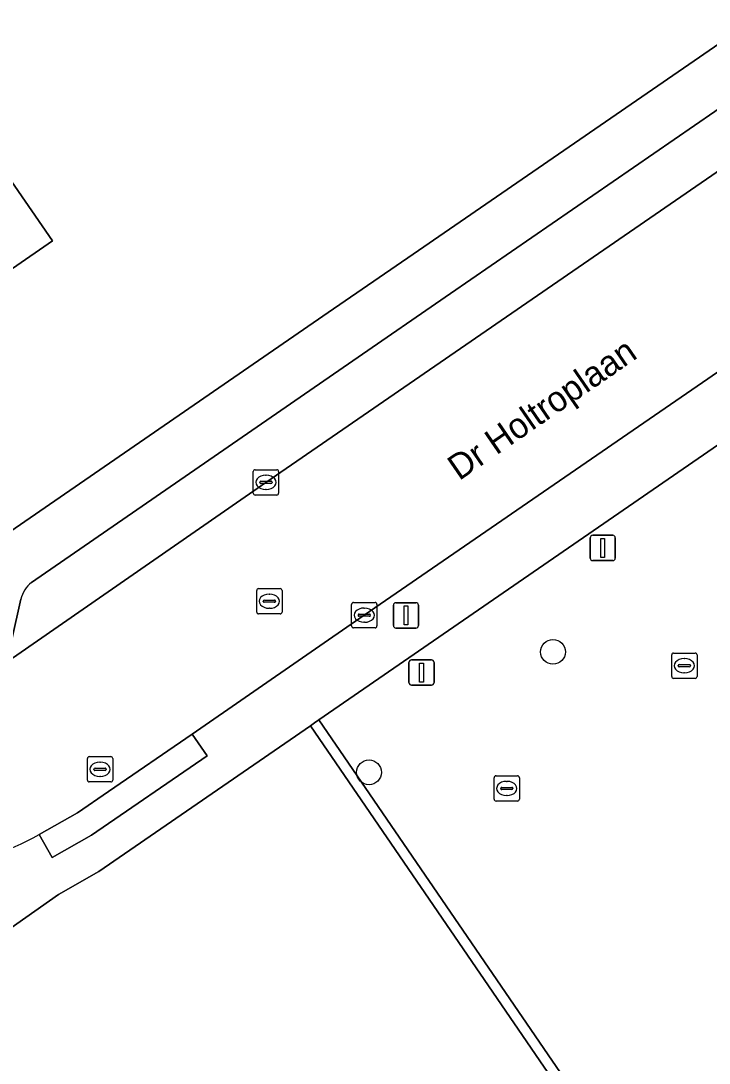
# Model space of a CAD drawing. Extents: x 157445 to 158888, y 383061 to 384688.
# Drawn here: x 157954.1 to 157981.3, y 383307.41 to 383348.55 of the extents above; entities that cross this region are included whole.
import ezdxf

# ---------------------------------------------------------------- set-up
doc = ezdxf.new("R2010")
doc.units = 0
for name, color, linetype in [('IMGEO_Boom', 7, 'Continuous'), ('IMGEO_Erf', 7, 'Continuous'), ('IMGEO_Groenvoorziening', 7, 'Continuous'), ('IMGEO_Haag', 7, 'Continuous'), ('IMGEO_Kolk', 7, 'Continuous'), ('IMGEO_Lichtmast', 7, 'Continuous'), ('IMGEO_Openbare_ruimte_label', 7, 'Continuous'), ('IMGEO_Pand', 7, 'Continuous'), ('IMGEO_Parkeervlak_open', 7, 'Continuous'), ('IMGEO_Rijbaan_lokaal_open', 7, 'Continuous'), ('IMGEO_Rioolput', 7, 'Continuous'), ('IMGEO_Voetpad_open', 7, 'Continuous')]:
    doc.layers.add(name, color=color, linetype=linetype)

msp = doc.modelspace()

# ---------------------------------------------------------------- linework, layer by layer
at = {"layer": 'IMGEO_Boom'}
for centre in [(157975.128, 383323.645), (157967.861, 383318.888)]:
    msp.add_circle(centre, 0.489, dxfattribs=at)
at = {"layer": 'IMGEO_Erf'}
for points in [[(157867.433, 383432.258), (157908.666, 383372.402), (157939.64, 383327.608), (157940.949, 383325.715), (157950.145, 383325.96), (157966.252, 383337.038), (157969.609, 383339.347), (158000, 383360.249), (158003.024, 383362.329), (158006.393, 383364.646), (158017.962, 383372.552), (158018.659, 383373.03), (158024.393, 383376.961), (158024.278, 383377.131)], [(157976.607, 383304.584), (157965.542, 383320.73), (157957.186, 383314.977), (157955.59, 383314.069), (157951.478, 383311.189), (157932.838, 383314.613), (157928.425, 383320.955), (157925.669, 383324.951), (157909.683, 383348.132), (157898.462, 383364.319), (157895.075, 383369.235), (157890.311, 383376.164), (157886.385, 383381.901), (157886.267, 383381.935), (157881.344, 383389.058), (157877.36, 383394.852), (157877.384, 383395.064), (157877.163, 383395.127), (157872.582, 383395.96), (157873.507, 383400.495), (157873.121, 383401.062), (157849.565, 383405.324)]]:
    msp.add_lwpolyline(points, dxfattribs=at)
for points in [[(157930.882, 383371.648), (157932.707, 383368.999), (157934.428, 383370.184), (157943.305, 383357.333), (157946.676, 383352.453), (157955.361, 383339.866), (157950.942, 383336.831), (157943.141, 383331.454), (157920.388, 383364.411), (157928.195, 383369.805)], [(158031.472, 383366.06), (158028.831, 383364.233), (158021.703, 383359.301), (158000, 383344.449), (157965.872, 383320.956), (157976.937, 383304.81), (158003.515, 383265.798), (158003.35, 383265.685), (158004.018, 383264.72), (158015.19, 383272.388), (158043.805, 383292.029), (158043.622, 383292.299), (158058.514, 383302.399), (158065.833, 383307.363), (158065.113, 383316.794), (158063.441, 383319.452), (158058.575, 383326.723), (158045.965, 383345.025)]]:
    msp.add_lwpolyline(points, close=True, dxfattribs=at)
at = {"layer": 'IMGEO_Groenvoorziening'}
msp.add_lwpolyline([(157965.872, 383320.956), (157965.707, 383320.843), (157965.542, 383320.73), (157976.607, 383304.584), (158003.179, 383265.58), (158003.35, 383265.685), (158003.515, 383265.798), (157976.937, 383304.81)], close=True, dxfattribs=at)
at = {"layer": 'IMGEO_Haag'}
msp.add_lwpolyline([(157965.872, 383320.956), (157965.707, 383320.843), (157965.542, 383320.73), (157976.607, 383304.584), (158003.179, 383265.58), (158003.35, 383265.685), (158003.515, 383265.798), (157976.937, 383304.81)], close=True, dxfattribs=at)
at = {"layer": 'IMGEO_Kolk'}
for p, q in [((157963.288, 383329.909), (157963.288, 383330.761)), ((157963.363, 383330.835), (157964.215, 383330.835)), ((157964.289, 383330.761), (157964.289, 383329.909)), ((157963.547, 383330.329), (157963.547, 383330.341)), ((157963.59, 383330.378), (157963.988, 383330.378)), ((157963.776, 383330.615), (157963.801, 383330.615)), ((157964.031, 383330.341), (157964.031, 383330.329)), ((157963.985, 383330.292), (157963.587, 383330.292)), ((157963.799, 383330.055), (157963.774, 383330.055)), ((157964.215, 383329.835), (157963.363, 383329.835)), ((157967.173, 383324.667), (157967.173, 383325.519)), ((157967.248, 383325.593), (157968.1, 383325.593)), ((157968.174, 383325.519), (157968.174, 383324.667)), ((157967.432, 383325.087), (157967.432, 383325.099)), ((157967.87, 383325.05), (157967.472, 383325.05)), ((157967.475, 383325.136), (157967.873, 383325.136)), ((157967.661, 383325.373), (157967.686, 383325.373)), ((157967.916, 383325.099), (157967.916, 383325.087)), ((157968.1, 383324.593), (157967.248, 383324.593)), ((157967.684, 383324.813), (157967.659, 383324.813)), ((157979.817, 383322.671), (157979.817, 383323.523)), ((157979.892, 383323.597), (157980.744, 383323.597)), ((157980.305, 383323.377), (157980.33, 383323.377)), ((157980.818, 383323.523), (157980.818, 383322.671)), ((157980.076, 383323.091), (157980.076, 383323.103)), ((157980.514, 383323.054), (157980.116, 383323.054)), ((157980.119, 383323.14), (157980.517, 383323.14)), ((157980.56, 383323.103), (157980.56, 383323.091)), ((157980.744, 383322.597), (157979.892, 383322.597)), ((157980.328, 383322.817), (157980.303, 383322.817)), ((157972.803, 383317.826), (157972.803, 383318.678)), ((157972.878, 383318.752), (157973.73, 383318.752)), ((157973.291, 383318.532), (157973.316, 383318.532)), ((157973.804, 383318.678), (157973.804, 383317.826)), ((157973.062, 383318.246), (157973.062, 383318.258)), ((157973.5, 383318.209), (157973.102, 383318.209)), ((157973.105, 383318.295), (157973.503, 383318.295)), ((157973.546, 383318.258), (157973.546, 383318.246)), ((157973.73, 383317.752), (157972.878, 383317.752)), ((157973.314, 383317.972), (157973.289, 383317.972))]:
    msp.add_line(p, q, dxfattribs=at)
for points in [[(157963.288, 383329.909), (157963.288, 383330.761)], [(157963.363, 383330.835), (157964.215, 383330.835)], [(157964.289, 383330.761), (157964.289, 383329.909)], [(157964.215, 383329.835), (157963.363, 383329.835)], [(157967.173, 383324.667), (157967.173, 383325.519)], [(157967.248, 383325.593), (157968.1, 383325.593)], [(157968.174, 383325.519), (157968.174, 383324.667)], [(157968.1, 383324.593), (157967.248, 383324.593)], [(157979.817, 383322.671), (157979.817, 383323.523)], [(157979.892, 383323.597), (157980.744, 383323.597)], [(157980.818, 383323.523), (157980.818, 383322.671)], [(157980.744, 383322.597), (157979.892, 383322.597)], [(157972.803, 383317.826), (157972.803, 383318.678)], [(157972.878, 383318.752), (157973.73, 383318.752)], [(157973.804, 383318.678), (157973.804, 383317.826)], [(157973.73, 383317.752), (157972.878, 383317.752)]]:
    msp.add_lwpolyline(points, dxfattribs=at)
for centre, radius, start, end in [((157963.365, 383330.759), 0.0765, 91.552, 178.448), ((157963.365, 383330.759), 0.0765, 91.552, 178.448), ((157964.213, 383330.759), 0.0765, 1.552, 88.448), ((157964.213, 383330.759), 0.0765, 1.552, 88.448), ((157963.587, 383330.338), 0.0403, 85.8775, 175.7526), ((157963.584, 383330.328), 0.0366, 178.938, 274.7102), ((157963.988, 383330.335), 0.043, 264.8664, 352.4533), ((157963.992, 383330.34), 0.0386, 1.7309, 96.639), ((157963.365, 383329.911), 0.0765, 181.552, 268.448), ((157963.365, 383329.911), 0.0765, 181.552, 268.448), ((157964.213, 383329.911), 0.0765, 271.552, 358.448), ((157964.213, 383329.911), 0.0765, 271.552, 358.448), ((157967.25, 383325.517), 0.0765, 91.552, 178.448), ((157967.25, 383325.517), 0.0765, 91.552, 178.448), ((157968.098, 383325.517), 0.0765, 1.552, 88.448), ((157968.098, 383325.517), 0.0765, 1.552, 88.448), ((157967.472, 383325.096), 0.0403, 85.8775, 175.7526), ((157967.469, 383325.086), 0.0366, 178.938, 274.7102), ((157967.873, 383325.093), 0.043, 264.8664, 352.4533), ((157967.877, 383325.098), 0.0386, 1.7309, 96.639), ((157967.25, 383324.669), 0.0765, 181.552, 268.448), ((157967.25, 383324.669), 0.0765, 181.552, 268.448), ((157968.098, 383324.669), 0.0765, 271.552, 358.448), ((157968.098, 383324.669), 0.0765, 271.552, 358.448), ((157979.894, 383323.521), 0.0765, 91.552, 178.448), ((157979.894, 383323.521), 0.0765, 91.552, 178.448), ((157980.742, 383323.521), 0.0765, 1.552, 88.448), ((157980.742, 383323.521), 0.0765, 1.552, 88.448), ((157980.116, 383323.1), 0.0403, 85.8775, 175.7526), ((157980.113, 383323.09), 0.0366, 178.938, 274.7102), ((157980.517, 383323.097), 0.043, 264.8664, 352.4533), ((157980.521, 383323.102), 0.0386, 1.7309, 96.639), ((157979.894, 383322.673), 0.0765, 181.552, 268.448), ((157979.894, 383322.673), 0.0765, 181.552, 268.448), ((157980.742, 383322.673), 0.0765, 271.552, 358.448), ((157980.742, 383322.673), 0.0765, 271.552, 358.448), ((157972.88, 383318.676), 0.0765, 91.552, 178.448), ((157972.88, 383318.676), 0.0765, 91.552, 178.448), ((157973.728, 383318.676), 0.0765, 1.552, 88.448), ((157973.728, 383318.676), 0.0765, 1.552, 88.448), ((157973.102, 383318.255), 0.0403, 85.8775, 175.7526), ((157973.099, 383318.245), 0.0366, 178.938, 274.7102), ((157973.503, 383318.252), 0.043, 264.8664, 352.4533), ((157973.507, 383318.257), 0.0386, 1.7309, 96.639), ((157972.88, 383317.828), 0.0765, 181.552, 268.448), ((157972.88, 383317.828), 0.0765, 181.552, 268.448), ((157973.728, 383317.828), 0.0765, 271.552, 358.448), ((157973.728, 383317.828), 0.0765, 271.552, 358.448)]:
    msp.add_arc(centre, radius, start, end, dxfattribs=at)
for centre, major_axis, ratio, start_param, end_param in [((157963.775, 383330.335), (-0.387, 0.002), 0.722429, 4.712389, 7.853982), ((157963.8, 383330.335), (-0.39, 0.002), 0.717154, 1.570796, 4.712389), ((157967.66, 383325.093), (-0.387, 0.002), 0.722429, 4.712389, 7.853982), ((157967.685, 383325.093), (-0.39, 0.002), 0.717154, 1.570796, 4.712389), ((157980.304, 383323.097), (-0.387, 0.002), 0.722429, 4.712389, 7.853982), ((157980.329, 383323.097), (-0.39, 0.002), 0.717154, 1.570796, 4.712389), ((157973.29, 383318.252), (-0.387, 0.002), 0.722429, 4.712389, 7.853982), ((157973.315, 383318.252), (-0.39, 0.002), 0.717154, 1.570796, 4.712389)]:
    msp.add_ellipse(centre, major_axis=major_axis, ratio=ratio, start_param=start_param, end_param=end_param, dxfattribs=at)
at = {"layer": 'IMGEO_Lichtmast'}
for p, q in [((157976.598, 383327.347), (157976.598, 383328.147)), ((157976.598, 383328.147), (157976.598, 383327.347)), ((157976.698, 383328.247), (157977.488, 383328.247)), ((157977.488, 383328.247), (157976.698, 383328.247)), ((157977.588, 383328.147), (157977.588, 383327.347)), ((157977.588, 383327.347), (157977.588, 383328.147)), ((157977.488, 383327.247), (157976.698, 383327.247)), ((157976.698, 383327.247), (157977.488, 383327.247)), ((157968.823, 383324.684), (157968.823, 383325.484)), ((157968.823, 383325.484), (157968.823, 383324.684)), ((157968.923, 383325.584), (157969.713, 383325.584)), ((157969.713, 383325.584), (157968.923, 383325.584)), ((157969.813, 383325.484), (157969.813, 383324.684)), ((157969.813, 383324.684), (157969.813, 383325.484)), ((157969.713, 383324.584), (157968.923, 383324.584)), ((157968.923, 383324.584), (157969.713, 383324.584)), ((157969.538, 383323.329), (157970.328, 383323.329)), ((157970.328, 383323.329), (157969.538, 383323.329)), ((157969.438, 383322.429), (157969.438, 383323.229)), ((157969.438, 383323.229), (157969.438, 383322.429)), ((157970.428, 383323.229), (157970.428, 383322.429)), ((157970.428, 383322.429), (157970.428, 383323.229)), ((157970.328, 383322.329), (157969.538, 383322.329)), ((157969.538, 383322.329), (157970.328, 383322.329))]:
    msp.add_line(p, q, dxfattribs=at)
for points in [[(157977.018, 383328.122), (157977.168, 383328.122), (157977.168, 383327.372), (157977.018, 383327.372), (157977.018, 383328.122)], [(157969.243, 383325.459), (157969.393, 383325.459), (157969.393, 383324.709), (157969.243, 383324.709), (157969.243, 383325.459)], [(157969.858, 383323.204), (157970.008, 383323.204), (157970.008, 383322.454), (157969.858, 383322.454), (157969.858, 383323.204)]]:
    msp.add_lwpolyline(points, dxfattribs=at)
for centre, start, end in [((157976.698, 383328.147), 90, 180), ((157976.698, 383328.147), 90, 180), ((157977.488, 383328.147), 0, 90), ((157977.488, 383328.147), 360, 90), ((157976.698, 383327.347), 180, 270), ((157976.698, 383327.347), 180, 270), ((157977.488, 383327.347), 270, 0), ((157977.488, 383327.347), 270, 0), ((157968.923, 383325.484), 90, 180), ((157968.923, 383325.484), 90, 180), ((157969.713, 383325.484), 0, 90), ((157969.713, 383325.484), 360, 90), ((157968.923, 383324.684), 180, 270), ((157968.923, 383324.684), 180, 270), ((157969.713, 383324.684), 270, 0), ((157969.713, 383324.684), 270, 0), ((157969.538, 383323.229), 90, 180), ((157969.538, 383323.229), 90, 180), ((157970.328, 383323.229), 0, 90), ((157970.328, 383323.229), 360, 90), ((157969.538, 383322.429), 180, 270), ((157969.538, 383322.429), 180, 270), ((157970.328, 383322.429), 270, 0), ((157970.328, 383322.429), 270, 0)]:
    msp.add_arc(centre, 0.1, start, end, dxfattribs=at)
at = {"layer": 'IMGEO_Pand'}
msp.add_lwpolyline([(157928.195, 383369.805), (157920.388, 383364.411), (157943.141, 383331.454), (157950.942, 383336.831), (157955.361, 383339.866), (157946.676, 383352.453), (157943.305, 383357.333), (157934.428, 383370.184), (157932.707, 383368.999), (157930.882, 383371.648)], close=True, dxfattribs=at)
at = {"layer": 'IMGEO_Parkeervlak_open'}
for points in [[(157952.94, 383322.832), (157963.789, 383330.335), (158000, 383355.247), (158003.857, 383357.9), (158019.883, 383368.976), (158021.502, 383369.98)], [(158017.439, 383369.68), (158008.4, 383363.459), (158003.44, 383360.064), (158000, 383357.696), (157971.079, 383337.788), (157967.223, 383335.13), (157954.529, 383326.381)], [(157954.104, 383325.722), (157953.748, 383324.126)]]:
    msp.add_lwpolyline(points, dxfattribs=at)
msp.add_arc((157955.198, 383325.483), 1.12, 126.6899, 167.6729, dxfattribs=at)
at = {"layer": 'IMGEO_Rijbaan_lokaal_open'}
for points in [[(157987.062, 383338.426), (157997.151, 383345.376), (158000, 383347.342), (158007.061, 383352.214), (158007.261, 383352.343), (158023.353, 383363.453), (158023.781, 383363.663), (158028.034, 383366.58), (158030.046, 383367.961), (158026.452, 383373.415), (158022.035, 383370.35), (158021.502, 383369.98), (158019.883, 383368.976), (158003.857, 383357.9), (158000, 383355.247), (157963.789, 383330.335), (157952.94, 383322.832)], [(157954.825, 383316.435), (157956.345, 383317.296), (157957.573, 383318.133), (157960.873, 383320.401), (157967.673, 383325.093), (157987.062, 383338.426)]]:
    msp.add_lwpolyline(points, dxfattribs=at)
msp.add_arc((157948.408, 383328.069), 13.287, 280.6399, 298.88, dxfattribs=at)
at = {"layer": 'IMGEO_Rioolput'}
for p, q in [((157963.423, 383325.218), (157963.423, 383326.07)), ((157963.498, 383326.144), (157964.35, 383326.144)), ((157963.911, 383325.924), (157963.936, 383325.924)), ((157964.424, 383326.07), (157964.424, 383325.218)), ((157963.682, 383325.638), (157963.682, 383325.65)), ((157964.12, 383325.601), (157963.722, 383325.601)), ((157963.725, 383325.687), (157964.123, 383325.687)), ((157964.166, 383325.65), (157964.166, 383325.638)), ((157964.35, 383325.144), (157963.498, 383325.144)), ((157963.934, 383325.364), (157963.909, 383325.364)), ((157956.735, 383318.582), (157956.735, 383319.434)), ((157956.81, 383319.508), (157957.662, 383319.508)), ((157957.223, 383319.288), (157957.248, 383319.288)), ((157957.736, 383319.434), (157957.736, 383318.582)), ((157956.994, 383319.002), (157956.994, 383319.014)), ((157957.432, 383318.965), (157957.034, 383318.965)), ((157957.037, 383319.051), (157957.435, 383319.051)), ((157957.478, 383319.014), (157957.478, 383319.002)), ((157957.662, 383318.508), (157956.81, 383318.508)), ((157957.246, 383318.728), (157957.221, 383318.728))]:
    msp.add_line(p, q, dxfattribs=at)
for points in [[(157963.423, 383325.218), (157963.423, 383326.07)], [(157963.498, 383326.144), (157964.35, 383326.144)], [(157964.424, 383326.07), (157964.424, 383325.218)], [(157964.35, 383325.144), (157963.498, 383325.144)], [(157956.735, 383318.582), (157956.735, 383319.434)], [(157956.81, 383319.508), (157957.662, 383319.508)], [(157957.736, 383319.434), (157957.736, 383318.582)], [(157957.662, 383318.508), (157956.81, 383318.508)]]:
    msp.add_lwpolyline(points, dxfattribs=at)
for centre, radius, start, end in [((157963.5, 383326.068), 0.0765, 91.552, 178.448), ((157963.5, 383326.068), 0.0765, 91.552, 178.448), ((157964.348, 383326.068), 0.0765, 1.552, 88.448), ((157964.348, 383326.068), 0.0765, 1.552, 88.448), ((157963.722, 383325.647), 0.0403, 85.8775, 175.7526), ((157963.719, 383325.637), 0.0366, 178.938, 274.7102), ((157964.123, 383325.644), 0.043, 264.8664, 352.4533), ((157964.127, 383325.649), 0.0386, 1.7309, 96.639), ((157963.5, 383325.22), 0.0765, 181.552, 268.448), ((157963.5, 383325.22), 0.0765, 181.552, 268.448), ((157964.348, 383325.22), 0.0765, 271.552, 358.448), ((157964.348, 383325.22), 0.0765, 271.552, 358.448), ((157956.812, 383319.432), 0.0765, 91.552, 178.448), ((157956.812, 383319.432), 0.0765, 91.552, 178.448), ((157957.66, 383319.432), 0.0765, 1.552, 88.448), ((157957.66, 383319.432), 0.0765, 1.552, 88.448), ((157957.034, 383319.011), 0.0403, 85.8775, 175.7526), ((157957.031, 383319.001), 0.0366, 178.938, 274.7102), ((157957.435, 383319.008), 0.043, 264.8664, 352.4533), ((157957.439, 383319.013), 0.0386, 1.7309, 96.639), ((157956.812, 383318.584), 0.0765, 181.552, 268.448), ((157956.812, 383318.584), 0.0765, 181.552, 268.448), ((157957.66, 383318.584), 0.0765, 271.552, 358.448), ((157957.66, 383318.584), 0.0765, 271.552, 358.448)]:
    msp.add_arc(centre, radius, start, end, dxfattribs=at)
for centre, major_axis, ratio, start_param, end_param in [((157963.91, 383325.644), (-0.387, 0.002), 0.722429, 4.712389, 7.853982), ((157963.935, 383325.644), (-0.39, 0.002), 0.717154, 1.570796, 4.712389), ((157957.222, 383319.008), (-0.387, 0.002), 0.722429, 4.712389, 7.853982), ((157957.247, 383319.008), (-0.39, 0.002), 0.717154, 1.570796, 4.712389)]:
    msp.add_ellipse(centre, major_axis=major_axis, ratio=ratio, start_param=start_param, end_param=end_param, dxfattribs=at)
at = {"layer": 'IMGEO_Voetpad_open'}
for points in [[(158021.502, 383369.98), (158022.035, 383370.35), (158026.452, 383373.415), (158024.393, 383376.961), (158018.659, 383373.03), (158017.962, 383372.552), (158006.393, 383364.646), (158003.024, 383362.329), (158000, 383360.249), (157969.609, 383339.347), (157966.252, 383337.038), (157950.145, 383325.96), (157940.949, 383325.715), (157939.64, 383327.608), (157936.465, 383325.145)], [(158000, 383344.449), (158021.703, 383359.301), (158028.831, 383364.233), (158031.472, 383366.06), (158030.046, 383367.961), (158028.034, 383366.58), (158023.781, 383363.663), (158023.353, 383363.453), (158007.261, 383352.343), (158007.061, 383352.214), (158007.652, 383351.358), (157997.742, 383344.52), (157997.151, 383345.376), (157987.062, 383338.426), (157967.673, 383325.093), (157960.873, 383320.401), (157961.461, 383319.543), (157956.896, 383316.413), (157955.338, 383315.53), (157954.825, 383316.435)], [(157954.529, 383326.381), (157967.223, 383335.13), (157971.079, 383337.788), (158000, 383357.696)], [(157909.683, 383348.132), (157925.669, 383324.951), (157928.425, 383320.955), (157932.838, 383314.613), (157951.478, 383311.189), (157955.59, 383314.069), (157957.186, 383314.977), (157965.542, 383320.73), (157965.707, 383320.843), (157965.872, 383320.956), (158000, 383344.449)], [(157953.748, 383324.126), (157954.104, 383325.722)]]:
    msp.add_lwpolyline(points, dxfattribs=at)
msp.add_lwpolyline([(157960.873, 383320.401), (157957.573, 383318.133), (157956.345, 383317.296), (157954.825, 383316.435), (157955.338, 383315.53), (157956.896, 383316.413), (157961.461, 383319.543)], close=True, dxfattribs=at)
for centre, radius, start, end in [((157955.198, 383325.483), 1.12, 126.6899, 167.6729), ((157948.408, 383328.069), 13.287, 280.6399, 298.88)]:
    msp.add_arc(centre, radius, start, end, dxfattribs=at)

# ---------------------------------------------------------------- texts
at = {"layer": 'IMGEO_Openbare_ruimte_label'}
msp.add_text('Dr Holtroplaan', height=1, rotation=34.5646, dxfattribs=at).set_placement((157971.421, 383330.382))

doc.saveas('drawing.dxf')
